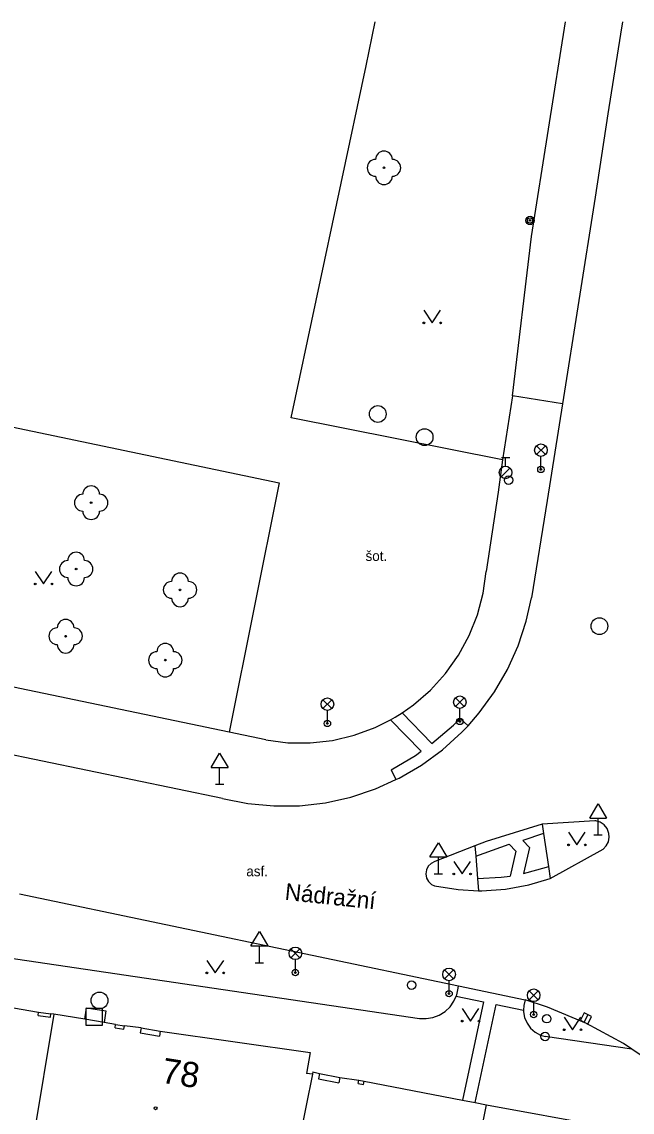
# Model space of a CAD drawing. Extents: x -642282 to -641982, y -1041678 to -1041427.
# Drawn here: x -642244.2 to -642207.7, y -1041493.9 to -1041428.9 of the extents above; entities that cross this region are included whole.
import ezdxf

# ---------------------------------------------------------------- set-up
doc = ezdxf.new("R2010")
doc.units = 0
for name, color, linetype in [('Budovy', 7, 'Continuous'), ('Popis povrchů', 7, 'Continuous'), ('Popis ulice', 7, 'Continuous'), ('Popis ČP_ ČE', 7, 'Continuous'), ('Pris-HUP', 7, 'Continuous'), ('Rozhraní ploch 1', 7, 'Continuous'), ('Rozhraní ploch 2', 7, 'Continuous'), ('Sloupy_označník', 7, 'Continuous'), ('Zeleň - stromy', 7, 'Continuous'), ('Znaky doprava', 7, 'Continuous'), ('Znaky kanalizace', 7, 'Continuous'), ('Znaky voda', 7, 'Continuous'), ('Značky doprava', 7, 'Continuous'), ('Značky KM', 7, 'Continuous'), ('Značky předmětů', 7, 'Continuous'), ('Šachty ner_', 7, 'Continuous')]:
    doc.layers.add(name, color=color, linetype=linetype)

msp = doc.modelspace()

# ---------------------------------------------------------------- linework, layer by layer
at = {"layer": 'Budovy'}
for p, q in [((-642244.65, -1041487.68), (-642243.16, -1041487.93)), ((-642242.235, -1041488.049), (-642244.025, -1041498.781)), ((-642243.16, -1041487.93), (-642242.42, -1041488.02)), ((-642242.235, -1041488.049), (-642242.42, -1041488.02)), ((-642240.404, -1041488.353), (-642242.235, -1041488.049)), ((-642239.247, -1041488.546), (-642240.404, -1041488.353)), ((-642238.56, -1041488.66), (-642239.247, -1041488.546)), ((-642238.56, -1041488.66), (-642238.03, -1041488.74)), ((-642237.04, -1041488.87), (-642238.03, -1041488.74)), ((-642237.04, -1041488.87), (-642237.089, -1041489.166)), ((-642237.04, -1041488.87), (-642235.89, -1041489.06)), ((-642237.089, -1041489.166), (-642235.939, -1041489.356)), ((-642235.89, -1041489.06), (-642235.939, -1041489.356)), ((-642235.89, -1041489.06), (-642226.95, -1041490.34)), ((-642226.95, -1041490.34), (-642227.17, -1041491.58)), ((-642226.8, -1041491.625), (-642227.17, -1041491.58)), ((-642226.78, -1041491.49), (-642226.8, -1041491.625)), ((-642226.78, -1041491.49), (-642226.39, -1041491.58)), ((-642226.39, -1041491.58), (-642226.45, -1041491.9)), ((-642226.39, -1041491.58), (-642225.17, -1041491.82)), ((-642226.8, -1041491.625), (-642228.742, -1041501.118)), ((-642226.45, -1041491.9), (-642225.23, -1041492.14)), ((-642225.17, -1041491.82), (-642225.23, -1041492.14)), ((-642225.17, -1041491.82), (-642224.04, -1041491.99)), ((-642224.04, -1041491.99), (-642223.72, -1041492.05)), ((-642223.72, -1041492.05), (-642217.86, -1041493.17)), ((-642219.104, -1041506.76), (-642216.43, -1041493.46)), ((-642217.86, -1041493.17), (-642217.11, -1041493.32)), ((-642217.11, -1041493.32), (-642216.43, -1041493.46)), ((-642216.43, -1041493.46), (-642209.45, -1041494.73))]:
    msp.add_line(p, q, dxfattribs=at)
at = {"layer": 'Pris-HUP'}
for p, q in [((-642243.184, -1041488.129), (-642243.16, -1041487.93)), ((-642243.184, -1041488.129), (-642242.444, -1041488.219)), ((-642242.444, -1041488.219), (-642242.42, -1041488.02)), ((-642238.59, -1041488.858), (-642238.56, -1041488.66)), ((-642238.59, -1041488.858), (-642238.06, -1041488.938)), ((-642238.06, -1041488.938), (-642238.03, -1041488.74)), ((-642224.077, -1041492.187), (-642224.04, -1041491.99)), ((-642224.077, -1041492.187), (-642223.757, -1041492.247)), ((-642223.757, -1041492.247), (-642223.72, -1041492.05))]:
    msp.add_line(p, q, dxfattribs=at)
at = {"layer": 'Rozhraní ploch 1'}
for p, q in [((-642213.74, -1041441.69), (-642211.721, -1041428.899)), ((-642208.312, -1041428.899), (-642208.43, -1041429.64)), ((-642208.43, -1041429.64), (-642209.18, -1041434.39)), ((-642209.18, -1041434.39), (-642209.95, -1041439.36)), ((-642209.95, -1041439.36), (-642211.89, -1041451.66)), ((-642214.88, -1041451.19), (-642213.74, -1041441.69)), ((-642211.89, -1041451.66), (-642214.88, -1041451.19)), ((-642211.89, -1041451.66), (-642212.8, -1041457.43)), ((-642215.74, -1041456.93), (-642216.45, -1041461.66)), ((-642212.8, -1041457.43), (-642213.74, -1041463.24)), ((-642231.773, -1041471.239), (-642252.953, -1041466.835)), ((-642215.953, -1041468.84), (-642215.174, -1041467.5)), ((-642232.19, -1041475.2), (-642264.81, -1041468.43)), ((-642221.45, -1041470.08), (-642219.68, -1041471.91)), ((-642222.15, -1041470.5), (-642220.33, -1041472.38)), ((-642217.99, -1041470.43), (-642217.53, -1041470.86)), ((-642229.6, -1041471.7), (-642231.773, -1041471.239)), ((-642222.12, -1041473.49), (-642221.83, -1041474.07)), ((-642213.018, -1041477.286), (-642214.26, -1041477.69)), ((-642212.63, -1041479.96), (-642209.47, -1041478.22)), ((-642244.29, -1041480.87), (-642218.1, -1041486.35)), ((-642245.63, -1041484.58), (-642220.43, -1041488.3)), ((-642218.1, -1041486.35), (-642214.11, -1041487.19)), ((-642218.23, -1041486.97), (-642216.6, -1041487.31)), ((-642216.6, -1041487.31), (-642217.86, -1041493.17)), ((-642217.11, -1041493.32), (-642215.85, -1041487.47)), ((-642215.85, -1041487.47), (-642214.22, -1041487.81)), ((-642207.762, -1041490.132), (-642212.93, -1041489.38))]:
    msp.add_line(p, q, dxfattribs=at)
for points in [[(-642214.88, -1041451.19), (-642215.476, -1041455.006), (-642215.74, -1041456.93)], [(-642220.778, -1041469.604), (-642219.77, -1041468.732), (-642218.873, -1041467.745), (-642218.1, -1041466.659), (-642217.464, -1041465.487), (-642216.972, -1041464.248), (-642216.632, -1041462.958), (-642216.45, -1041461.66)], [(-642215.174, -1041467.5), (-642214.538, -1041466.087), (-642214.05, -1041464.616), (-642213.74, -1041463.24)], [(-642223.054, -1041474.617), (-642221.83, -1041474.07), (-642221.642, -1041473.979), (-642220.304, -1041473.198), (-642219.053, -1041472.283), (-642217.902, -1041471.244), (-642217.53, -1041470.86), (-642216.866, -1041470.092), (-642215.953, -1041468.84)], [(-642229.6, -1041471.7), (-642228.277, -1041471.868), (-642226.944, -1041471.877), (-642225.619, -1041471.727), (-642224.322, -1041471.418), (-642223.071, -1041470.957), (-642222.15, -1041470.5), (-642221.884, -1041470.35), (-642221.45, -1041470.08), (-642220.778, -1041469.604)], [(-642219.68, -1041471.91), (-642218.392, -1041470.817), (-642217.99, -1041470.43)], [(-642222.12, -1041473.49), (-642220.672, -1041472.621), (-642220.33, -1041472.38)], [(-642232.19, -1041475.2), (-642230.669, -1041475.499), (-642229.126, -1041475.64), (-642227.577, -1041475.622), (-642226.037, -1041475.443), (-642224.524, -1041475.108), (-642223.054, -1041474.617)], [(-642209.96, -1041476.52), (-642213.1, -1041476.72), (-642213.018, -1041477.286), (-642212.727, -1041479.239), (-642212.63, -1041479.96)], [(-642209.47, -1041478.22), (-642209.279, -1041478.022), (-642209.152, -1041477.778), (-642209.1, -1041477.508), (-642209.12, -1041477.27), (-642209.233, -1041476.98), (-642209.407, -1041476.767), (-642209.634, -1041476.612), (-642209.896, -1041476.528), (-642209.96, -1041476.52)], [(-642213.1, -1041476.72), (-642216.445, -1041477.764), (-642217.13, -1041478.01), (-642219.51, -1041478.95)], [(-642217.07, -1041478.64), (-642215.08, -1041477.91), (-642214.68, -1041478.34), (-642215.01, -1041479.82)], [(-642214.26, -1041477.69), (-642213.87, -1041478.11), (-642214.21, -1041479.66)], [(-642217.13, -1041478.01), (-642217.07, -1041478.64), (-642216.962, -1041479.969), (-642216.9, -1041480.69)], [(-642219.51, -1041478.95), (-642219.731, -1041479.058), (-642219.905, -1041479.23), (-642220.016, -1041479.449), (-642220.051, -1041479.692), (-642220.006, -1041479.934), (-642219.886, -1041480.148), (-642219.705, -1041480.313), (-642219.52, -1041480.4)], [(-642214.21, -1041479.66), (-642212.847, -1041479.282), (-642212.727, -1041479.239)], [(-642216.962, -1041479.969), (-642215.55, -1041479.892), (-642215.01, -1041479.82)], [(-642219.52, -1041480.4), (-642218.124, -1041480.624), (-642216.9, -1041480.69), (-642216.711, -1041480.689), (-642215.3, -1041480.595), (-642213.909, -1041480.342), (-642212.63, -1041479.96)], [(-642220.43, -1041488.3), (-642220.024, -1041488.312), (-642219.623, -1041488.244), (-642219.244, -1041488.1), (-642218.899, -1041487.884), (-642218.604, -1041487.605), (-642218.369, -1041487.273), (-642218.23, -1041486.97), (-642218.204, -1041486.902), (-642218.114, -1041486.506), (-642218.1, -1041486.35)], [(-642214.11, -1041487.19), (-642214.202, -1041487.539), (-642214.22, -1041487.81), (-642214.216, -1041487.9), (-642214.15, -1041488.255), (-642214.007, -1041488.588), (-642213.796, -1041488.88), (-642213.525, -1041489.119), (-642213.208, -1041489.293), (-642212.93, -1041489.38)], [(-642210.468, -1041488.611), (-642212.784, -1041487.636), (-642214.11, -1041487.19)], [(-642204.22, -1041492.79), (-642206.166, -1041491.2), (-642207.762, -1041490.132), (-642208.255, -1041489.803), (-642210.468, -1041488.611)]]:
    msp.add_lwpolyline(points, dxfattribs=at)
at = {"layer": 'Rozhraní ploch 2'}
for p, q in [((-642223.616, -1041431.524), (-642223.066, -1041428.899)), ((-642228.075, -1041452.494), (-642223.616, -1041431.524)), ((-642249.894, -1041451.961), (-642228.798, -1041456.376)), ((-642215.476, -1041455.006), (-642228.075, -1041452.494)), ((-642228.798, -1041456.376), (-642231.773, -1041471.239))]:
    msp.add_line(p, q, dxfattribs=at)
msp.add_lwpolyline([(-642240.404, -1041488.353), (-642240.3, -1041487.68), (-642239.14, -1041487.85), (-642239.247, -1041488.546)], dxfattribs=at)
at = {"layer": 'Sloupy_označník'}
for centre, radius in [((-642213.83, -1041440.74), 0.25), ((-642213.83, -1041440.74), 0.158), ((-642213.83, -1041440.74), 0.05), ((-642215.11, -1041456.22), 0.25), ((-642220.9, -1041486.32), 0.25), ((-642212.83, -1041488.32), 0.25), ((-642212.93, -1041489.38), 0.25)]:
    msp.add_circle(centre, radius, dxfattribs=at)
at = {"layer": 'Zeleň - stromy'}
for centre in [(-642222.545, -1041437.601), (-642240.019, -1041457.563), (-642240.915, -1041461.516), (-642234.715, -1041462.76), (-642241.54, -1041465.521), (-642235.595, -1041466.947)]:
    msp.add_circle(centre, 0.05, dxfattribs=at)
for centre, start, end in [((-642222.545, -1041437.101), 0, 180), ((-642223.045, -1041437.601), 90, 270), ((-642222.045, -1041437.601), 270, 90), ((-642222.545, -1041438.101), 180, 0), ((-642240.519, -1041457.563), 90, 270), ((-642240.019, -1041457.063), 0, 180), ((-642239.519, -1041457.563), 270, 90), ((-642240.019, -1041458.063), 180, 0), ((-642241.415, -1041461.516), 90, 270), ((-642240.915, -1041461.016), 0, 180), ((-642240.415, -1041461.516), 270, 90), ((-642240.915, -1041462.016), 180, 0), ((-642235.215, -1041462.76), 90, 270), ((-642234.715, -1041462.26), 0, 180), ((-642234.215, -1041462.76), 270, 90), ((-642234.715, -1041463.26), 180, 0), ((-642241.54, -1041465.021), 0, 180), ((-642242.04, -1041465.521), 90, 270), ((-642241.04, -1041465.521), 270, 90), ((-642241.54, -1041466.021), 180, 0), ((-642235.595, -1041466.447), 0, 180), ((-642236.095, -1041466.947), 90, 270), ((-642235.095, -1041466.947), 270, 90), ((-642235.595, -1041467.447), 180, 0)]:
    msp.add_arc(centre, 0.5, start, end, dxfattribs=at)
at = {"layer": 'Znaky doprava'}
for p, q in [((-642213.445, -1041454.165), (-642212.915, -1041454.695)), ((-642213.445, -1041454.695), (-642212.915, -1041454.165)), ((-642213.18, -1041455.58), (-642213.18, -1041454.805)), ((-642226.185, -1041469.305), (-642225.655, -1041469.835)), ((-642226.185, -1041469.835), (-642225.655, -1041469.305)), ((-642218.285, -1041469.185), (-642217.755, -1041469.715)), ((-642218.285, -1041469.715), (-642217.755, -1041469.185)), ((-642225.92, -1041470.72), (-642225.92, -1041469.945)), ((-642218.02, -1041470.6), (-642218.02, -1041469.825)), ((-642228.095, -1041484.155), (-642227.565, -1041484.685)), ((-642228.095, -1041484.685), (-642227.565, -1041484.155)), ((-642227.83, -1041485.57), (-642227.83, -1041484.795)), ((-642218.925, -1041485.415), (-642218.395, -1041485.945)), ((-642218.925, -1041485.945), (-642218.395, -1041485.415)), ((-642218.66, -1041486.83), (-642218.66, -1041486.055)), ((-642213.875, -1041486.655), (-642213.345, -1041487.185)), ((-642213.875, -1041487.185), (-642213.345, -1041486.655)), ((-642213.61, -1041488.07), (-642213.61, -1041487.295))]:
    msp.add_line(p, q, dxfattribs=at)
for centre, radius in [((-642213.18, -1041454.43), 0.375), ((-642213.18, -1041455.58), 0.19), ((-642213.18, -1041455.58), 0.05), ((-642225.92, -1041469.57), 0.375), ((-642218.02, -1041469.45), 0.375), ((-642225.92, -1041470.72), 0.19), ((-642225.92, -1041470.72), 0.05), ((-642218.02, -1041470.6), 0.19), ((-642218.02, -1041470.6), 0.05), ((-642227.83, -1041484.42), 0.375), ((-642227.83, -1041485.57), 0.19), ((-642227.83, -1041485.57), 0.05), ((-642218.66, -1041485.68), 0.375), ((-642218.66, -1041486.83), 0.19), ((-642218.66, -1041486.83), 0.05), ((-642213.61, -1041486.92), 0.375), ((-642213.61, -1041488.07), 0.19), ((-642213.61, -1041488.07), 0.05)]:
    msp.add_circle(centre, radius, dxfattribs=at)
at = {"layer": 'Znaky kanalizace'}
msp.add_line((-642210.376, -1041488.077), (-642210.604, -1041488.523), dxfattribs=at)
msp.add_lwpolyline([(-642210.599, -1041487.964), (-642210.826, -1041488.409), (-642210.381, -1041488.636), (-642210.154, -1041488.191)], close=True, dxfattribs=at)
for centre in [(-642222.916, -1041452.276), (-642220.119, -1041453.654), (-642209.69, -1041464.92), (-642239.52, -1041487.23)]:
    msp.add_circle(centre, 0.5, dxfattribs=at)
at = {"layer": 'Znaky voda'}
for p, q in [((-642215.54, -1041454.86), (-642215.04, -1041454.86)), ((-642215.29, -1041455.385), (-642215.29, -1041454.86)), ((-642215.555, -1041456.025), (-642215.025, -1041455.495))]:
    msp.add_line(p, q, dxfattribs=at)
msp.add_circle((-642215.29, -1041455.76), 0.375, dxfattribs=at)
at = {"layer": 'Značky doprava'}
for p, q in [((-642232.85, -1041473.34), (-642232.35, -1041472.49)), ((-642232.35, -1041472.49), (-642231.85, -1041473.34)), ((-642232.85, -1041473.34), (-642231.85, -1041473.34)), ((-642232.35, -1041474.34), (-642232.35, -1041473.34)), ((-642232.6, -1041474.34), (-642232.1, -1041474.34)), ((-642210.27, -1041476.36), (-642209.77, -1041475.51)), ((-642209.77, -1041475.51), (-642209.27, -1041476.36)), ((-642210.27, -1041476.36), (-642209.27, -1041476.36)), ((-642209.77, -1041477.36), (-642209.77, -1041476.36)), ((-642219.8, -1041478.68), (-642219.3, -1041477.83)), ((-642219.3, -1041477.83), (-642218.8, -1041478.68)), ((-642210.02, -1041477.36), (-642209.52, -1041477.36)), ((-642219.8, -1041478.68), (-642218.8, -1041478.68)), ((-642219.3, -1041479.68), (-642219.3, -1041478.68)), ((-642219.55, -1041479.68), (-642219.05, -1041479.68)), ((-642230.48, -1041483.98), (-642229.98, -1041483.13)), ((-642229.98, -1041483.13), (-642229.48, -1041483.98)), ((-642230.48, -1041483.98), (-642229.48, -1041483.98)), ((-642229.98, -1041484.98), (-642229.98, -1041483.98)), ((-642230.23, -1041484.98), (-642229.73, -1041484.98))]:
    msp.add_line(p, q, dxfattribs=at)
at = {"layer": 'Značky KM'}
for p, q in [((-642220.164, -1041446.094), (-642219.664, -1041446.844)), ((-642219.664, -1041446.844), (-642219.164, -1041446.094)), ((-642243.357, -1041461.658), (-642242.857, -1041462.408)), ((-642242.857, -1041462.408), (-642242.357, -1041461.658)), ((-642211.53, -1041477.21), (-642211.03, -1041477.96)), ((-642211.03, -1041477.96), (-642210.53, -1041477.21)), ((-642218.38, -1041478.94), (-642217.88, -1041479.69)), ((-642217.88, -1041479.69), (-642217.38, -1041478.94)), ((-642233.11, -1041484.84), (-642232.61, -1041485.59)), ((-642232.61, -1041485.59), (-642232.11, -1041484.84)), ((-642217.875, -1041487.713), (-642217.375, -1041488.463)), ((-642217.375, -1041488.463), (-642216.875, -1041487.713)), ((-642211.79, -1041488.23), (-642211.29, -1041488.98)), ((-642211.29, -1041488.98), (-642210.79, -1041488.23))]:
    msp.add_line(p, q, dxfattribs=at)
for centre in [(-642220.164, -1041446.844), (-642219.164, -1041446.844), (-642243.357, -1041462.408), (-642242.357, -1041462.408), (-642211.53, -1041477.96), (-642210.53, -1041477.96), (-642218.38, -1041479.69), (-642217.38, -1041479.69), (-642233.11, -1041485.59), (-642232.11, -1041485.59), (-642217.875, -1041488.463), (-642216.875, -1041488.463), (-642211.79, -1041488.98), (-642210.79, -1041488.98)]:
    msp.add_circle(centre, 0.05, dxfattribs=at)
at = {"layer": 'Značky předmětů'}
msp.add_circle((-642236.174, -1041493.655), 0.0875, dxfattribs=at)
at = {"layer": 'Šachty ner_'}
msp.add_lwpolyline([(-642240.34, -1041488.71), (-642239.34, -1041488.71), (-642239.34, -1041487.71), (-642240.34, -1041487.71)], close=True, dxfattribs=at)

# ---------------------------------------------------------------- texts
at = {"layer": 'Popis povrchů'}
for s, p in [('šot.', (-642223.645, -1041461.035)), ('asf.', (-642230.76, -1041479.83))]:
    msp.add_text(s, height=0.6, dxfattribs=at).set_placement(p)
at = {"layer": 'Popis ulice'}
msp.add_text('Nádražní', height=1, rotation=353.9206, dxfattribs=at).set_placement((-642228.492, -1041481.229))
at = {"layer": 'Popis ČP_ ČE'}
msp.add_text('78', height=1.5, rotation=351.118, dxfattribs=at).set_placement((-642235.884, -1041492.123))

doc.saveas('drawing.dxf')
